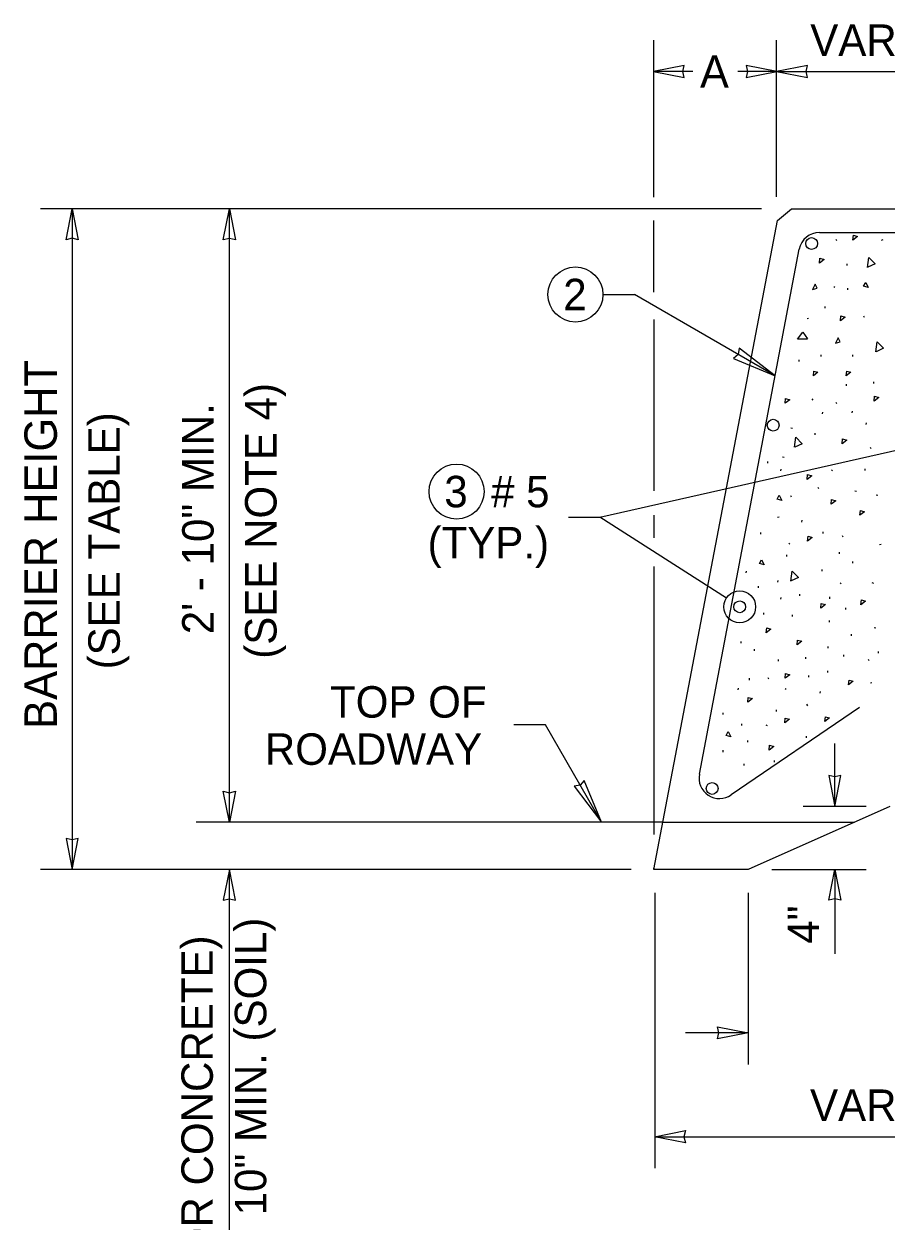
# Model space of a CAD drawing. Extents: x 99862 to 103151, y 100000 to 102076.
# Drawn here: x 101371 to 101810, y 100473 to 101082 of the extents above; entities that cross this region are included whole.
import ezdxf

# ---------------------------------------------------------------- set-up
doc = ezdxf.new("R2010")
doc.units = 0
for name, color, linetype in [('Level 10', 7, 'Continuous'), ('Level 13', 7, 'Continuous'), ('Level 15', 7, 'Continuous'), ('Level 16', 7, 'Continuous'), ('Level 2', 7, 'Continuous'), ('Level 20', 7, 'Continuous')]:
    doc.layers.add(name, color=color, linetype=linetype)

msp = doc.modelspace()

# ---------------------------------------------------------------- linework, layer by layer
at = {"layer": 'Level 10'}
for p, q in [((101776.05, 100976.02), (101846.51, 100976.02)), ((101714.88, 100700.49), (101765.74, 100967.48)), ((101796.44, 100734.28), (101731.1, 100689.84))]:
    msp.add_line(p, q, dxfattribs=at)
for centre in [(101771.99, 100970.36), (101752.45, 100877.96), (101735.42, 100785.56), (101721.37, 100693.16)]:
    msp.add_circle(centre, 3, dxfattribs=at)
for centre, start, end in [((101776.05, 100965.52), 90, 169.2157), ((101725.2, 100698.53), 169.2157, 304.2157)]:
    msp.add_arc(centre, 10.5, start, end, dxfattribs=at)
at = {"layer": 'Level 13'}
for p, q in [((101784.24, 100972.64), (101784.6, 100971.92)), ((101807.57, 100972.15), (101808.35, 100972.36)), ((101790.03, 100959.15), (101790.09, 100960.02)), ((101783.32, 100948.49), (101783.84, 100948.11)), ((101790.37, 100946.82), (101790.43, 100947.69)), ((101778.87, 100937.41), (101778.93, 100938.28)), ((101769.66, 100932.16), (101770.44, 100932.37)), ((101798.43, 100933.66), (101798.79, 100932.94)), ((101776.77, 100912.83), (101776.83, 100913.71)), ((101792.98, 100912.83), (101793.04, 100913.71)), ((101765.63, 100910.35), (101765.69, 100911.22)), ((101803.61, 100899.17), (101803.67, 100900.04)), ((101789.68, 100897.98), (101789.74, 100898.85)), ((101772.18, 100891.41), (101772.54, 100890.69)), ((101784.24, 100889.75), (101784.6, 100889.03)), ((101777.6, 100883.66), (101777.66, 100884.53)), ((101792.7, 100884.24), (101792.76, 100885.11)), ((101762.32, 100876.22), (101761.48, 100876.44)), ((101799.78, 100878.32), (101799.84, 100879.2)), ((101773.79, 100873.1), (101773.85, 100873.97)), ((101773.79, 100873.1), (101773.85, 100873.97)), ((101801.72, 100866.56), (101802.24, 100866.18)), ((101749.67, 100858.66), (101749.74, 100859.53)), ((101757.99, 100861.51), (101757.14, 100861.73)), ((101756.38, 100854.67), (101756.44, 100855.54)), ((101782.18, 100855.25), (101782.69, 100854.87)), ((101799.23, 100854.97), (101799.29, 100855.84)), ((101775.2, 100846.18), (101775.72, 100845.8)), ((101761.3, 100842.17), (101761.66, 100841.45)), ((101794.77, 100844.26), (101793.99, 100844.47)), ((101805.76, 100842.12), (101804.91, 100842.34)), ((101754.63, 100831.1), (101755.41, 100831.31)), ((101767.08, 100828.68), (101767.14, 100829.56)), ((101746.1, 100822.44), (101746.16, 100823.32)), ((101777.82, 100822.9), (101777.88, 100823.77)), ((101787.51, 100821.85), (101787.86, 100821.13)), ((101760.38, 100818.02), (101760.9, 100817.64)), ((101806.52, 100817.22), (101807.36, 100817.45)), ((101759.35, 100811.1), (101759.41, 100811.98)), ((101786.19, 100812.44), (101786.25, 100813.31)), ((101792.97, 100807.72), (101792.9, 100808.59)), ((101738.74, 100802.84), (101738.8, 100803.71)), ((101777.32, 100803.73), (101777.38, 100804.6)), ((101744.94, 100795.21), (101745, 100796.08)), ((101754.89, 100798.07), (101754.95, 100798.94)), ((101786.59, 100797.7), (101787.1, 100797.32)), ((101803.69, 100797.46), (101802.85, 100797.69)), ((101756.38, 100789.43), (101756.44, 100790.3)), ((101766, 100791.15), (101766.06, 100792.03)), ((101781.27, 100789.7), (101781.33, 100790.58)), ((101789.32, 100784.2), (101789.38, 100785.08)), ((101747.64, 100781.58), (101747.7, 100782.46)), ((101762.19, 100780.59), (101762.25, 100781.46)), ((101781.09, 100777.74), (101781.15, 100778.62)), ((101804.71, 100774.68), (101803.87, 100774.9)), ((101736.16, 100767.11), (101736.22, 100767.98)), ((101792.21, 100770.83), (101792.27, 100771.7)), ((101742.89, 100763.15), (101742.95, 100764.02)), ((101769.07, 100759.09), (101769.13, 100759.96)), ((101780.39, 100764.53), (101780.45, 100765.4)), ((101788.4, 100760.26), (101788.46, 100761.13)), ((101806.04, 100762.04), (101806.1, 100762.91)), ((101755.14, 100757.89), (101755.2, 100758.77)), ((101800.77, 100758.72), (101801.29, 100758.34)), ((101740.38, 100748.33), (101740.44, 100749.21)), ((101749.7, 100749.66), (101750.06, 100748.94)), ((101770.55, 100749.74), (101770.61, 100750.61)), ((101780.19, 100752.17), (101780.25, 100753.05)), ((101734.69, 100743.36), (101734.75, 100744.24)), ((101758.56, 100744.09), (101759.08, 100743.71)), ((101776.38, 100741.61), (101776.44, 100742.48)), ((101801.9, 100746.9), (101802.68, 100747.11)), ((101769.47, 100736), (101769.82, 100735.28)), ((101726.96, 100730.85), (101727.02, 100731.72)), ((101754.14, 100732.31), (101754.2, 100733.18)), ((101736.42, 100725.15), (101736.48, 100726.03)), ((101748.78, 100725.52), (101749.3, 100725.14)), ((101739.48, 100716.63), (101739.54, 100717.5)), ((101769.33, 100718.91), (101769.39, 100719.79)), ((101726.96, 100711.7), (101727.02, 100712.57)), ((101737.61, 100704.87), (101737.67, 100705.74)), ((101753.12, 100706.57), (101753.18, 100707.45))]:
    msp.add_line(p, q, dxfattribs=at)
for points in [[(101793.04, 100972.16), (101793.28, 100974.61), (101795.41, 100973.97), (101793.04, 100972.16)], [(101775.96, 100960.46), (101776.2, 100962.91), (101778.32, 100962.27), (101775.96, 100960.46)], [(101800.47, 100958.23), (101801.18, 100963.3), (101804.36, 100960.02), (101800.56, 100958.26)], [(101772.45, 100946.97), (101774.81, 100947.67), (101773.77, 100949.63), (101772.45, 100946.97)], [(101800.83, 100947.92), (101798.47, 100948.63), (101799.51, 100950.59), (101800.83, 100947.92)], [(101786.63, 100931.11), (101786.87, 100933.56), (101789, 100932.91), (101786.63, 100931.11)], [(101769.98, 100921.77), (101764.85, 100921.67), (101767.6, 100925.33), (101769.93, 100921.85)], [(101784.18, 100919.71), (101786.54, 100920.42), (101785.5, 100922.38), (101784.18, 100919.71)], [(101804.69, 100915.28), (101805.39, 100920.35), (101808.57, 100917.07), (101804.77, 100915.31)], [(101772.87, 100903.06), (101773.11, 100905.51), (101775.24, 100904.87), (101772.87, 100903.06)], [(101789.6, 100903.06), (101789.85, 100905.51), (101791.97, 100904.87), (101789.6, 100903.06)], [(101758.51, 100889.13), (101758.75, 100891.58), (101760.87, 100890.94), (101758.51, 100889.13)], [(101803.81, 100890.24), (101804.05, 100892.69), (101806.17, 100892.04), (101803.81, 100890.24)], [(101763.34, 100866.74), (101764.05, 100871.82), (101767.23, 100868.53), (101763.43, 100866.77)], [(101787.51, 100868.55), (101787.76, 100871), (101789.88, 100870.36), (101787.51, 100868.55)], [(101769.74, 100850.38), (101769.98, 100852.83), (101772.1, 100852.19), (101769.74, 100850.38)], [(101756.77, 100839.65), (101754.41, 100840.35), (101755.45, 100842.31), (101756.77, 100839.65)], [(101781.95, 100837.7), (101782.19, 100840.15), (101784.32, 100839.5), (101781.95, 100837.7)], [(101796.59, 100832.13), (101796.83, 100834.58), (101798.95, 100833.94), (101796.59, 100832.13)], [(101769.93, 100819.04), (101770.17, 100821.49), (101772.3, 100820.85), (101769.93, 100819.04)], [(101747.89, 100806.88), (101745.53, 100807.58), (101746.57, 100809.55), (101747.89, 100806.88)], [(101761.42, 100798.67), (101762.13, 100803.74), (101765.31, 100800.46), (101761.51, 100798.7)], [(101776.63, 100784.86), (101776.87, 100787.31), (101778.99, 100786.67), (101776.63, 100784.86)], [(101797.08, 100786.64), (101797.33, 100789.09), (101799.45, 100788.45), (101797.08, 100786.64)], [(101748.89, 100772.38), (101749.14, 100774.83), (101751.26, 100774.19), (101748.89, 100772.38)], [(101764.61, 100766.21), (101764.85, 100768.66), (101766.98, 100768.01), (101764.61, 100766.21)], [(101758.5, 100749.19), (101758.74, 100751.64), (101760.87, 100751), (101758.5, 100749.19)], [(101790.82, 100745.88), (101791.06, 100748.33), (101793.18, 100747.69), (101790.82, 100745.88)], [(101739.47, 100737.04), (101739.71, 100739.49), (101741.84, 100738.85), (101739.47, 100737.04)], [(101778.8, 100727.23), (101779.04, 100729.68), (101781.16, 100729.03), (101778.8, 100727.23)], [(101758.33, 100726.53), (101758.58, 100728.99), (101760.7, 100728.34), (101758.33, 100726.53)], [(101730.88, 100719.41), (101728.53, 100720.12), (101729.56, 100722.08), (101730.88, 100719.41)], [(101750.38, 100712.67), (101750.62, 100715.12), (101752.75, 100714.47), (101750.38, 100712.67)]]:
    msp.add_lwpolyline(points, dxfattribs=at)
at = {"layer": 'Level 15'}
for p, q in [((101691.76, 100994.02), (101691.76, 101073.83)), ((101754.21, 100994.13), (101754.21, 101073.83)), ((101711.51, 101057.83), (101691.51, 101057.83)), ((101754.38, 101057.83), (101734.38, 101057.83)), ((101754.38, 101057.83), (101868.89, 101057.83)), ((101746.57, 100988.02), (101379.77, 100988)), ((101395.77, 100988.02), (101395.77, 100652.02)), ((101475.77, 100676.02), (101475.77, 100988)), ((101691.76, 100945.62), (101691.76, 100982.02)), ((101665.82, 100944.44), (101681.82, 100944.44)), ((101753.47, 100903.07), (101681.82, 100944.44)), ((101691.75, 100931.78), (101691.75, 100844.59)), ((101648.25, 100831.19), (101664.25, 100831.19)), ((101691.75, 100832.18), (101691.75, 100820.69)), ((101691.75, 100806.01), (101691.75, 100669.71)), ((101636.54, 100725.61), (101620.54, 100725.61)), ((101665.17, 100676.02), (101636.54, 100725.61)), ((101783.76, 100684.02), (101783.76, 100716.02)), ((101799.76, 100684.02), (101767.76, 100684.02)), ((101680.19, 100652), (101379.78, 100652)), ((101475.77, 100265.58), (101475.77, 100652)), ((101691.76, 100652.02), (101691.76, 100652.57)), ((101751.76, 100652.02), (101799.76, 100652.02)), ((101783.76, 100652.02), (101783.76, 100609.04)), ((101692.19, 100640.02), (101692.19, 100500.03)), ((101739.76, 100640.02), (101739.76, 100552.82)), ((101739.76, 100568.82), (101707.76, 100568.82)), ((101692.04, 100516.03), (101931.34, 100516.03))]:
    msp.add_line(p, q, dxfattribs=at)
for points in [[(101691.51, 101057.83), (101707.24, 101054.75), (101706.51, 101057.83), (101707.24, 101060.92)], [(101754.38, 101057.83), (101738.66, 101060.92), (101739.39, 101057.83), (101738.66, 101054.75)], [(101754.21, 101057.83), (101769.93, 101054.75), (101769.2, 101057.83), (101769.93, 101060.92)], [(101395.81, 100988.02), (101398.89, 100972.3), (101395.81, 100973.02), (101392.72, 100972.3)], [(101475.77, 100988), (101478.86, 100972.28), (101475.77, 100973.01), (101472.69, 100972.28)], [(101753.47, 100903.07), (101735.19, 100917.07), (101734.61, 100913.96), (101732.21, 100911.9)], [(101783.76, 100684.02), (101786.85, 100699.75), (101783.76, 100699.02), (101780.68, 100699.75)], [(101665.17, 100676.02), (101656.34, 100697.28), (101654.28, 100694.88), (101651.17, 100694.3)], [(101475.77, 100676.02), (101472.69, 100691.75), (101475.77, 100691.02), (101478.85, 100691.75)], [(101395.81, 100652.02), (101398.89, 100667.75), (101395.81, 100667.02), (101392.72, 100667.75)], [(101475.77, 100652), (101472.69, 100636.28), (101475.77, 100637.01), (101478.85, 100636.28)], [(101783.76, 100652.02), (101786.85, 100636.3), (101783.76, 100637.02), (101780.68, 100636.3)], [(101739.76, 100568.82), (101724.04, 100565.74), (101724.77, 100568.82), (101724.04, 100571.91)], [(101692.04, 100516.03), (101707.76, 100519.12), (101707.04, 100516.03), (101707.76, 100512.95)]]:
    msp.add_lwpolyline(points, close=True, dxfattribs=at)
msp.add_lwpolyline([(101728.61, 100789.92), (101664.25, 100831.19), (101863.19, 100876.17)], dxfattribs=at)
msp.add_circle((101735.42, 100785.56), 8.08, dxfattribs=at)
at = {"layer": 'Level 16'}
msp.add_lwpolyline([(101696.32, 100676.02), (101458.96, 100676.02)], dxfattribs=at)
at = {"layer": 'Level 2'}
for p, q in [((101754.64, 100982.13), (101761.76, 100988.02)), ((101761.76, 100988.02), (101861.76, 100988.02)), ((101691.76, 100652.02), (101754.64, 100982.13)), ((101696.32, 100676.02), (101793.76, 100676.02))]:
    msp.add_line(p, q, dxfattribs=at)
msp.add_lwpolyline([(101811.76, 100684.02), (101739.76, 100652.02), (101691.76, 100652.02)], dxfattribs=at)
at = {"layer": 'Level 20'}
for centre in [(101651.82, 100944.44), (101591.38, 100844.19)]:
    msp.add_circle(centre, 14, dxfattribs=at)

# ---------------------------------------------------------------- texts
at = {"layer": 'Level 15'}
msp.add_text('A', height=16.5, dxfattribs=at).set_placement((101715.2, 101049.58))
at = {"layer": 'Level 20'}
for s, p in [('VARIES', (101771.3, 101065.83)), ('2', (101645.64, 100936.44)), (' 3  # 5', (101579.18, 100836.19)), ('(TYP.)', (101576.63, 100810.19)), ('VARIES', (101771.19, 100524.03))]:
    msp.add_text(s, height=16, dxfattribs=at).set_placement(p)
for s, height, rotation, p in [('BARRIER HEIGHT', 16.5, 90, (101388.03, 100723.52)), ('(SEE NOTE 4)', 16, 90, (101499.77, 100759.13)), ('(SEE TABLE)', 16, 90, (101420.03, 100753.75)), ('2\' - 10" MIN.', 16, 90, (101467.77, 100771.62)), ('TOP OF', 16, 360, (101526.99, 100729.19)), ('ROADWAY', 16, 360, (101493.83, 100705.19)), ('4"', 16, 90, (101775.77, 100614.16)), ('10" MIN. (SOIL)', 16, 90, (101494.57, 100476)), ('3" MIN. (ASPHALT OR CONCRETE)', 16, 90, (101467.37, 100266.06))]:
    msp.add_text(s, height=height, rotation=rotation, dxfattribs=at).set_placement(p)

doc.saveas('drawing.dxf')
